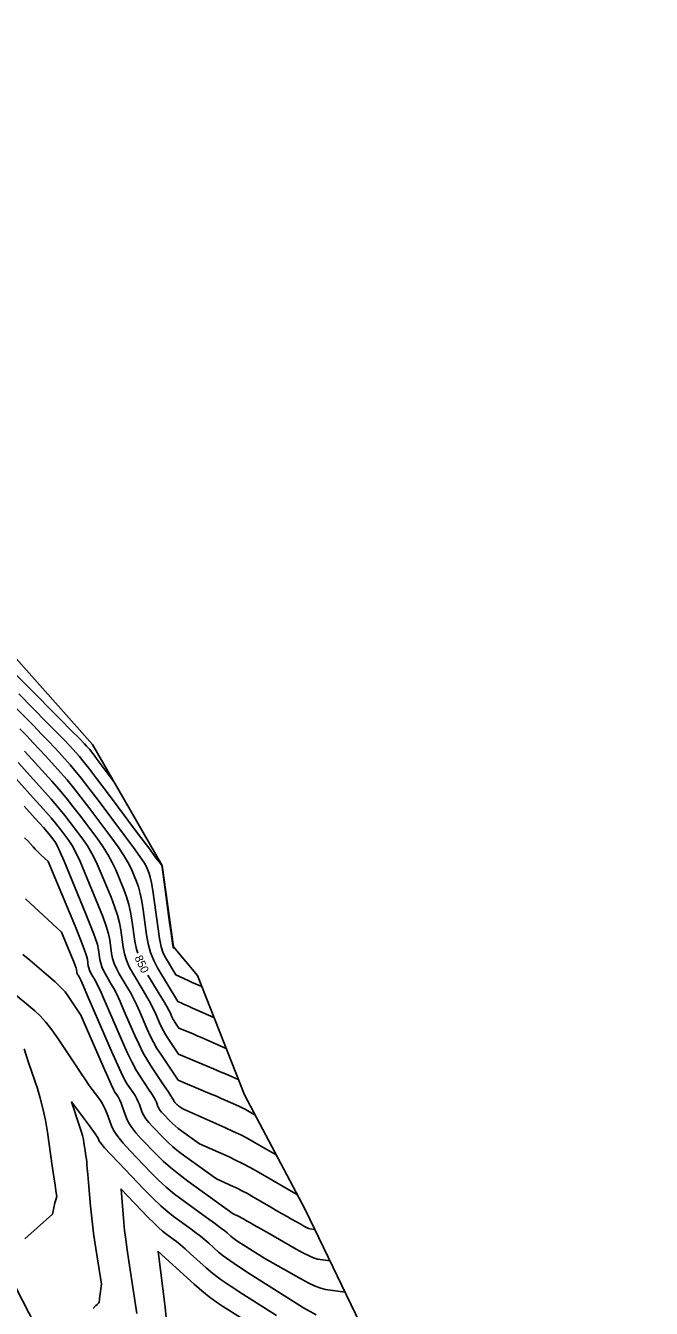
# Model space of a CAD drawing. Extents: x 1715724 to 1716561, y 394063 to 395906.
# Drawn here: x 1715978.1 to 1716086.3, y 395212.3 to 395434.3 of the extents above; entities that cross this region are included whole.
import ezdxf

# ---------------------------------------------------------------- set-up
doc = ezdxf.new("R2010")
doc.units = 0
for name, color, linetype in [('DT_X_Contour_Major', 7, 'Continuous'), ('DT_X_Contour_Minor', 7, 'Continuous'), ('DT_X_TIN_Hull', 7, 'Continuous'), ('GE_P_CL_10', 7, 'Continuous')]:
    doc.layers.add(name, color=color, linetype=linetype)

msp = doc.modelspace()

# ---------------------------------------------------------------- linework, layer by layer
at = {"layer": 'DT_X_Contour_Major'}
for points in [[(1715977.94, 395308.7), (1715979.19, 395307.33), (1715982.62, 395303.52), (1715983.89, 395302.08), (1715985.11, 395300.63), (1715986.29, 395299.16), (1715987.43, 395297.68), (1715990.41, 395293.7), (1715991.45, 395292.24), (1715992.35, 395290.83), (1715993.09, 395289.48), (1715993.69, 395288.19), (1715995.08, 395284.8), (1715995.56, 395283.52), (1715995.96, 395282.21), (1715996.27, 395280.88), (1715996.5, 395279.52), (1715996.99, 395275.87), (1715997.26, 395274.49), (1715997.49, 395273.76)], [(1715978.06, 395283.15), (1715984.31, 395277.39), (1715986.09, 395273.09), (1715986.43, 395272.26), (1715986.67, 395271.63), (1715986.83, 395271.19), (1715986.89, 395270.94), (1715986.95, 395270.54), (1715986.97, 395270.39), (1715987.02, 395270.24), (1715987.09, 395270.09), (1715987.17, 395269.94), (1715987.41, 395269.54), (1715987.63, 395269.09), (1715988.1, 395268.04), (1715988.82, 395266.39), (1715989.8, 395264.14), (1715992.75, 395257.33), (1715993.76, 395255.03), (1715994.59, 395253.23), (1715995.24, 395251.93), (1715995.7, 395251.13), (1715996.69, 395249.66), (1715997.03, 395249.12), (1715997.33, 395248.59), (1715997.59, 395248.07), (1715997.79, 395247.56), (1715998.28, 395246.22), (1715998.53, 395245.69), (1715998.9, 395245.1), (1715999.41, 395244.46), (1716000.05, 395243.75), (1716001.93, 395241.8), (1716002.69, 395241.05), (1716003.57, 395240.28), (1716004.56, 395239.48), (1716005.67, 395238.65), (1716011.11, 395234.71), (1716014.03, 395233.42), (1716014.72, 395233.09), (1716015.53, 395232.67), (1716016.47, 395232.16), (1716017.52, 395231.56), (1716020.52, 395229.82), (1716021.58, 395229.2), (1716022.51, 395228.66), (1716023.32, 395228.2), (1716024.01, 395227.8), (1716025.69, 395226.85), (1716026.26, 395226.54), (1716026.72, 395226.3), (1716027.06, 395226.15), (1716027.29, 395226.09), (1716028.12, 395225.97)], [(1715999.27, 395269.97), (1716001.22, 395266.74), (1716001.96, 395265.51), (1716002.52, 395264.55), (1716002.9, 395263.88), (1716003.1, 395263.48), (1716003.4, 395262.78), (1716003.52, 395262.53), (1716003.65, 395262.28), (1716003.78, 395262.05), (1716003.92, 395261.83), (1716004.6, 395260.82), (1716006.8, 395259.9), (1716007.31, 395259.68), (1716007.89, 395259.43), (1716008.54, 395259.15), (1716009.26, 395258.83), (1716012.79, 395257.27)], [(1716002.44, 395210.69), (1716002.22, 395212.53), (1716001.03, 395222.17), (1716007.28, 395216.51), (1716008.6, 395215.36), (1716009.88, 395214.32), (1716011.11, 395213.41), (1716012.31, 395212.6), (1716015.25, 395210.75)]]:
    msp.add_lwpolyline(points, dxfattribs=at)
at = {"layer": 'DT_X_Contour_Minor'}
for points in [[(1715976.53, 395321.9), (1715978.43, 395319.99), (1715984.13, 395314.22), (1715986.01, 395312.31), (1715987.4, 395310.9), (1715988.28, 395310), (1715988.66, 395309.61), (1715989, 395309.23), (1715989.19, 395309), (1715989.5, 395308.6), (1715989.95, 395308.02), (1715990.51, 395307.27), (1715993.45, 395303.34)], [(1715976.91, 395318.62), (1715981.79, 395313.68), (1715983.44, 395312), (1715984.75, 395310.66), (1715985.69, 395309.68), (1715986.29, 395309.04), (1715987.4, 395307.8), (1715988.02, 395307.06), (1715989.04, 395305.76), (1715990.45, 395303.91), (1715992.27, 395301.5), (1715997.64, 395294.33), (1715999.4, 395291.97), (1716000.66, 395290.29), (1716001.42, 395289.28), (1716001.68, 395288.93), (1716001.69, 395288.9), (1716001.73, 395288.63), (1716002.02, 395286.52), (1716003.02, 395279.06), (1716003.27, 395277.22), (1716003.45, 395275.89), (1716003.57, 395275.09), (1716003.62, 395274.8), (1716003.69, 395274.68), (1716003.92, 395274.57)], [(1715975.38, 395317.26), (1715979.45, 395313.14), (1715980.88, 395311.69), (1715982.1, 395310.42), (1715983.11, 395309.35), (1715983.92, 395308.47), (1715985.81, 395306.37), (1715986.64, 395305.4), (1715987.73, 395304.05), (1715989.07, 395302.33), (1715990.66, 395300.22), (1715995.23, 395294.12), (1715996.75, 395292.06), (1715997.89, 395290.47), (1715998.65, 395289.34), (1715999.01, 395288.68), (1715999.49, 395287.54), (1715999.67, 395286.93), (1715999.88, 395285.96), (1716000.1, 395284.64), (1716000.34, 395282.96), (1716001.01, 395278), (1716001.28, 395276.29), (1716001.58, 395274.89), (1716001.91, 395273.79), (1716002.28, 395273), (1716004.07, 395270.04), (1716006.25, 395269.03), (1716006.68, 395268.83), (1716007.05, 395268.66), (1716007.35, 395268.52), (1716007.6, 395268.42), (1716008.57, 395267.99)], [(1715977.11, 395312.6), (1715978.31, 395311.37), (1715979.44, 395310.18), (1715980.53, 395309.03), (1715981.55, 395307.9), (1715984.22, 395304.95), (1715985.27, 395303.74), (1715986.42, 395302.34), (1715987.68, 395300.74), (1715989.04, 395298.95), (1715992.82, 395293.91), (1715994.1, 395292.15), (1715995.12, 395290.65), (1715995.87, 395289.41), (1715996.35, 395288.43), (1715997.29, 395286.17), (1715997.62, 395285.22), (1715997.92, 395284.09), (1715998.19, 395282.76), (1715998.42, 395281.24), (1715999, 395276.93), (1715999.29, 395275.36), (1715999.7, 395273.88), (1716000.26, 395272.5), (1716000.94, 395271.21), (1716004.46, 395265.4), (1716005.11, 395265.09), (1716005.33, 395264.99), (1716005.72, 395264.82), (1716006.26, 395264.58), (1716006.98, 395264.26), (1716010.68, 395262.63)], [(1715976.82, 395306.76), (1715981.03, 395302.09), (1715982.51, 395300.42), (1715983.8, 395298.92), (1715984.91, 395297.58), (1715985.82, 395296.4), (1715988, 395293.5), (1715988.8, 395292.33), (1715989.57, 395291.02), (1715990.31, 395289.55), (1715991.02, 395287.94), (1715992.88, 395283.44), (1715993.51, 395281.82), (1715994, 395280.34), (1715994.36, 395279), (1715994.58, 395277.81), (1715994.98, 395274.8), (1715995.2, 395273.67), (1715995.55, 395272.55), (1715996.03, 395271.42), (1715996.65, 395270.3), (1715998.46, 395267.3), (1715999.09, 395266.22), (1715999.63, 395265.25), (1716000.08, 395264.38), (1716000.44, 395263.61), (1716001.27, 395261.69), (1716001.6, 395260.99), (1716001.94, 395260.32), (1716002.31, 395259.68), (1716002.69, 395259.07), (1716004.55, 395256.3), (1716010.61, 395253.75), (1716011.78, 395253.26), (1716012.69, 395252.88), (1716013.33, 395252.6), (1716013.72, 395252.44), (1716014.9, 395251.92)], [(1715974.45, 395306.19), (1715979.43, 395300.66), (1715981.13, 395298.76), (1715982.5, 395297.2), (1715983.52, 395295.99), (1715984.21, 395295.13), (1715985.59, 395293.29), (1715986.15, 395292.42), (1715986.8, 395291.2), (1715987.54, 395289.62), (1715988.36, 395287.69), (1715990.68, 395282.07), (1715991.46, 395280.12), (1715992.04, 395278.47), (1715992.44, 395277.13), (1715992.66, 395276.09), (1715992.97, 395273.73), (1715993.14, 395272.85), (1715993.42, 395271.97), (1715993.8, 395271.09), (1715994.28, 395270.21), (1715995.7, 395267.86), (1715996.23, 395266.94), (1715996.75, 395265.95), (1715997.27, 395264.88), (1715997.78, 395263.74), (1715999.14, 395260.6), (1715999.67, 395259.45), (1716000.23, 395258.35), (1716000.83, 395257.3), (1716001.47, 395256.31), (1716004.51, 395251.79), (1716009.24, 395249.8), (1716010.21, 395249.39), (1716011.1, 395249), (1716011.91, 395248.65), (1716012.64, 395248.33), (1716014.48, 395247.51), (1716015.12, 395247.22), (1716015.66, 395246.97), (1716016.1, 395246.75), (1716016.43, 395246.56), (1716017.78, 395245.78)], [(1715977.84, 395299.23), (1715979.76, 395297.1), (1715981.19, 395295.49), (1715982.13, 395294.41), (1715982.59, 395293.86), (1715983.18, 395293.08), (1715983.5, 395292.51), (1715984.03, 395291.38), (1715984.76, 395289.69), (1715985.7, 395287.44), (1715988.48, 395280.7), (1715989.4, 395278.41), (1715990.08, 395276.59), (1715990.53, 395275.25), (1715990.73, 395274.37), (1715990.96, 395272.67), (1715991.09, 395272.03), (1715991.29, 395271.39), (1715991.56, 395270.76), (1715991.91, 395270.12), (1715992.93, 395268.42), (1715993.36, 395267.66), (1715993.87, 395266.65), (1715994.45, 395265.38), (1715995.12, 395263.87), (1715997.01, 395259.51), (1715997.73, 395257.94), (1715998.46, 395256.48), (1715999.22, 395255.14), (1715999.99, 395253.93), (1716002.06, 395250.84), (1716002.74, 395249.82), (1716003.24, 395249.07), (1716003.54, 395248.6), (1716003.66, 395248.4), (1716003.72, 395248.24), (1716003.75, 395248.18), (1716003.8, 395248.1), (1716003.86, 395248.03), (1716003.94, 395247.94), (1716004.16, 395247.7), (1716004.26, 395247.61), (1716004.36, 395247.52), (1716004.49, 395247.42), (1716004.62, 395247.32), (1716005.29, 395246.84), (1716012.55, 395243.61), (1716014.02, 395242.94), (1716015.32, 395242.31), (1716016.45, 395241.74), (1716017.4, 395241.21), (1716021.45, 395238.86)], [(1715977.94, 395293.74), (1715978.49, 395293.18), (1715979.43, 395292.15), (1715979.77, 395291.78), (1715980.1, 395291.43), (1715980.41, 395291.12), (1715980.7, 395290.85), (1715982.03, 395289.62), (1715986.71, 395278.3), (1715987.59, 395276.12), (1715988.23, 395274.46), (1715988.64, 395273.3), (1715988.81, 395272.66), (1715988.95, 395271.6), (1715989.03, 395271.21), (1715989.15, 395270.82), (1715989.32, 395270.42), (1715989.54, 395270.03), (1715990.17, 395268.98), (1715990.49, 395268.37), (1715990.98, 395267.34), (1715991.64, 395265.89), (1715992.46, 395264.01), (1715994.88, 395258.42), (1715995.75, 395256.48), (1715996.53, 395254.85), (1715997.23, 395253.54), (1715997.84, 395252.53), (1715999.37, 395250.25), (1715999.89, 395249.47), (1716000.29, 395248.83), (1716000.56, 395248.33), (1716000.73, 395247.98), (1716001, 395247.23), (1716001.14, 395246.93), (1716001.35, 395246.6), (1716001.64, 395246.24), (1716001.99, 395245.85), (1716003.05, 395244.75), (1716003.47, 395244.33), (1716003.97, 395243.9), (1716004.52, 395243.45), (1716005.15, 395242.98), (1716008.2, 395240.78), (1716013.29, 395238.51), (1716014.43, 395237.98), (1716015.65, 395237.36), (1716016.96, 395236.66), (1716018.37, 395235.86), (1716025.11, 395231.94)], [(1715977.62, 395273.55), (1715978.81, 395272.56), (1715982.09, 395269.81), (1715983.23, 395268.82), (1715984.17, 395267.91), (1715984.93, 395267.08), (1715985.49, 395266.33), (1715987.68, 395263.02), (1715991.56, 395254.06), (1715992.31, 395252.35), (1715992.9, 395251.06), (1715993.31, 395250.18), (1715993.56, 395249.73), (1715994, 395249.07), (1715994.18, 395248.77), (1715994.38, 395248.34), (1715994.61, 395247.8), (1715994.86, 395247.14), (1715995.56, 395245.21), (1715995.92, 395244.45), (1715996.46, 395243.6), (1715997.19, 395242.67), (1715998.11, 395241.66), (1716000.81, 395238.85), (1716001.91, 395237.78), (1716003.17, 395236.66), (1716004.6, 395235.51), (1716006.19, 395234.31), (1716014.03, 395228.65), (1716014.77, 395228.32), (1716014.95, 395228.24), (1716015.15, 395228.13), (1716015.39, 395228), (1716015.66, 395227.85), (1716016.42, 395227.41), (1716016.87, 395227.15), (1716017.66, 395226.7), (1716018.77, 395226.07), (1716020.21, 395225.24), (1716024.51, 395222.8), (1716025.97, 395222), (1716027.15, 395221.4), (1716028.04, 395221.02), (1716028.63, 395220.84), (1716030.74, 395220.54)], [(1715975.29, 395267.47), (1715979.68, 395263.8), (1715980.64, 395262.91), (1715981.63, 395261.81), (1715982.66, 395260.49), (1715983.72, 395258.96), (1715986.6, 395254.6), (1715987.6, 395253.1), (1715988.44, 395251.87), (1715989.11, 395250.9), (1715989.62, 395250.2), (1715990.76, 395248.7), (1715991.17, 395248.1), (1715991.54, 395247.45), (1715991.88, 395246.75), (1715992.19, 395245.99), (1715992.95, 395243.89), (1715993.37, 395243.03), (1715994.04, 395242.02), (1715994.98, 395240.87), (1715996.17, 395239.57), (1715999.69, 395235.9), (1716001.04, 395234.56), (1716002.43, 395233.29), (1716003.88, 395232.09), (1716005.37, 395230.95), (1716009.42, 395228.03), (1716010.78, 395227.04), (1716011.82, 395226.27), (1716012.54, 395225.72), (1716012.95, 395225.39), (1716013.61, 395224.78), (1716013.93, 395224.52), (1716014.39, 395224.19), (1716014.98, 395223.79), (1716015.72, 395223.32), (1716019.46, 395220.96), (1716025.8, 395217.35), (1716027.08, 395216.67), (1716028.2, 395216.14), (1716029.17, 395215.79), (1716029.97, 395215.6), (1716033.37, 395215.1)], [(1715977.95, 395224.36), (1715982.75, 395228.58), (1715983.06, 395230.01), (1715983.13, 395230.3), (1715983.19, 395230.55), (1715983.24, 395230.76), (1715983.28, 395230.93), (1715983.49, 395231.65), (1715983.4, 395232.32), (1715983.35, 395232.72), (1715983.22, 395233.63), (1715983.01, 395235.05), (1715982.72, 395236.98), (1715981.87, 395242.79), (1715981.52, 395244.9), (1715981.11, 395246.87), (1715980.65, 395248.69), (1715980.14, 395250.38), (1715978.69, 395254.68), (1715978.21, 395256.11), (1715977.86, 395257.19)], [(1715989.82, 395212.3), (1715990.28, 395212.8), (1715990.47, 395213), (1715990.78, 395213.27), (1715990.82, 395213.44), (1715990.83, 395213.52), (1715990.86, 395213.71), (1715990.9, 395214.01), (1715990.95, 395214.4), (1715991.22, 395216.48), (1715990.08, 395223.78), (1715989.85, 395225.34), (1715989.65, 395226.89), (1715989.48, 395228.44), (1715989.33, 395229.98), (1715988.99, 395234.09), (1715988.87, 395235.46), (1715988.78, 395236.5), (1715988.72, 395237.21), (1715988.68, 395237.59), (1715988.61, 395238.15), (1715988.58, 395238.4), (1715988.53, 395238.72), (1715988.48, 395239.12), (1715988.41, 395239.6), (1715988.2, 395240.98), (1715988.1, 395241.54), (1715987.94, 395242.21), (1715987.72, 395242.96), (1715987.44, 395243.82), (1715986.03, 395248.04), (1715989.17, 395243.89), (1715989.76, 395243.09), (1715990.21, 395242.46), (1715990.5, 395242.01), (1715990.65, 395241.74), (1715990.83, 395241.24), (1715991.09, 395240.87), (1715991.75, 395240.11), (1715992.79, 395238.98), (1715994.23, 395237.47), (1715998.57, 395232.95), (1716000.13, 395231.37), (1716001.52, 395230.04), (1716002.76, 395228.95), (1716003.85, 395228.1), (1716006.53, 395226.16), (1716007.49, 395225.45), (1716008.36, 395224.78), (1716009.13, 395224.16), (1716009.8, 395223.57), (1716011.47, 395222.05), (1716012.27, 395221.4), (1716013.42, 395220.57), (1716014.92, 395219.55), (1716016.77, 395218.37), (1716026.2, 395212.41), (1716028.37, 395211.18)], [(1715997.37, 395211.42), (1715997.13, 395212.94), (1715996.84, 395214.85), (1715995.96, 395220.45), (1715995.66, 395222.45), (1715995.42, 395224.23), (1715995.23, 395225.79), (1715995.1, 395227.15), (1715994.61, 395232.96), (1715999.32, 395228.06), (1716000.26, 395227.1), (1716001.08, 395226.31), (1716001.77, 395225.69), (1716002.33, 395225.24), (1716003.65, 395224.29), (1716004.21, 395223.86), (1716004.89, 395223.3), (1716005.71, 395222.59), (1716006.65, 395221.75), (1716009.33, 395219.33), (1716010.48, 395218.36), (1716011.93, 395217.27), (1716013.67, 395216.07), (1716015.7, 395214.75), (1716021.51, 395211.08)]]:
    msp.add_lwpolyline(points, dxfattribs=at)
at = {"layer": 'DT_X_TIN_Hull'}
msp.add_lwpolyline([(1716036.81, 395207.99), (1716026.44, 395229.43), (1716015.95, 395249.24), (1716007.82, 395269.9), (1716003.67, 395274.88), (1716001.74, 395288.94), (1715989.7, 395309.86), (1715975.1, 395326.33), (1715959.74, 395337.73), (1715947.5, 395351.97), (1715936.7, 395374.51), (1715936.34, 395375.27), (1715926.08, 395398.06), (1715925.19, 395400.05), (1715916.7, 395417.97), (1715910.92, 395433.61), (1715893.86, 395425.44), (1715886.84, 395422.34), (1715877.89, 395436.06)], dxfattribs=at)
at = {"layer": 'GE_P_CL_10'}
msp.add_line((1716249.46, 394685.42), (1715852.54, 395456.56), dxfattribs=at)

# ---------------------------------------------------------------- texts
at = {"layer": 'DT_X_Contour_Major'}
msp.add_text('850', height=1.4, rotation=295.1867, dxfattribs=at).set_placement((1715996.91, 395273))

doc.saveas('drawing.dxf')
